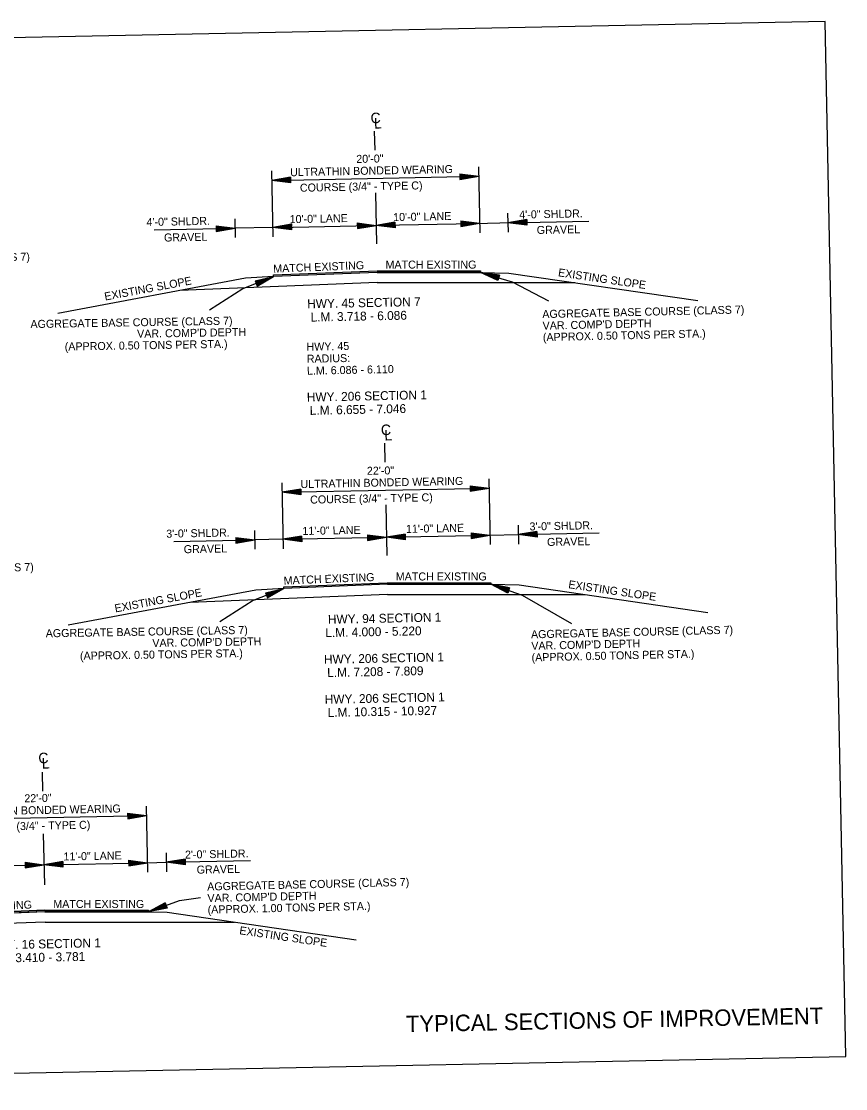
# Model space of a CAD drawing. Extents: x 174 to 869, y -36 to 177.
# Drawn here: x 606.8 to 694.4, y 60.6 to 174 of the extents above; entities that cross this region are included whole.
import ezdxf

# ---------------------------------------------------------------- set-up
doc = ezdxf.new("R2010")
doc.units = 0
for name, color, linetype in [('Default', 7, 'Continuous'), ('DSN_DRFT_Common-Annotations', 7, 'Continuous'), ('DSN_DRFT_Common-Line', 7, 'Continuous'), ('DSN_DRFT_Dimension', 7, 'Continuous'), ('SHET_Border-Text', 7, 'Continuous')]:
    doc.layers.add(name, color=color, linetype=linetype)

msp = doc.modelspace()

# ---------------------------------------------------------------- linework, layer by layer
at = {"layer": 'Default'}
for p, q in [((633.63, 146.84), (630.37, 145.54)), ((631.66, 146.38), (633.63, 146.84)), ((631.66, 146.38), (631.88, 145.82)), ((631.68, 146.33), (633.32, 146.72)), ((631.7, 146.28), (633, 146.59)), ((631.71, 146.24), (632.69, 146.46)), ((631.73, 146.19), (632.37, 146.34)), ((631.81, 146.01), (632.37, 146.34)), ((631.82, 145.96), (632.69, 146.46)), ((631.84, 145.91), (633, 146.59)), ((631.86, 145.87), (633.32, 146.72)), ((631.88, 145.82), (633.63, 146.84)), ((655.63, 147.28), (658.99, 146.29)), ((657.63, 147), (655.63, 147.28)), ((657.46, 146.43), (655.63, 147.28)), ((657.62, 146.95), (655.95, 147.19)), ((657.47, 146.48), (655.95, 147.19)), ((657.49, 146.52), (656.28, 147.09)), ((657.6, 146.91), (656.28, 147.09)), ((657.59, 146.86), (656.6, 147)), ((657.5, 146.57), (656.6, 147)), ((657.52, 146.62), (656.92, 146.9)), ((657.57, 146.81), (656.92, 146.9)), ((657.53, 146.67), (657.24, 146.8)), ((657.56, 146.76), (657.24, 146.8)), ((657.63, 147), (657.46, 146.43)), ((658.99, 146.29), (662.83, 144.28)), ((630.37, 145.54), (626.83, 143.27)), ((631.75, 146.14), (632.06, 146.22)), ((631.79, 146.05), (632.06, 146.22)), ((634.72, 113.71), (631.47, 112.42)), ((632.76, 113.25), (634.72, 113.71)), ((632.77, 113.21), (634.41, 113.59)), ((632.79, 113.16), (634.09, 113.46)), ((632.94, 112.79), (634.09, 113.46)), ((632.96, 112.74), (634.41, 113.59)), ((632.98, 112.7), (634.72, 113.71)), ((656.72, 114.15), (660.03, 113.01)), ((658.71, 113.79), (656.72, 114.15)), ((658.51, 113.22), (656.72, 114.15)), ((658.69, 113.74), (657.04, 114.05)), ((658.53, 113.27), (657.04, 114.05)), ((658.55, 113.32), (657.36, 113.93)), ((658.68, 113.69), (657.36, 113.93)), ((658.66, 113.64), (657.68, 113.83)), ((658.56, 113.36), (657.68, 113.83)), ((658.58, 113.41), (658, 113.72)), ((658.64, 113.6), (658, 113.72)), ((658.6, 113.46), (658.31, 113.61)), ((658.63, 113.55), (658.31, 113.61)), ((658.71, 113.79), (658.51, 113.22)), ((631.47, 112.42), (627.92, 110.15)), ((632.76, 113.25), (632.98, 112.7)), ((632.81, 113.11), (633.79, 113.34)), ((632.83, 113.06), (633.47, 113.22)), ((632.85, 113.02), (633.16, 113.09)), ((632.88, 112.93), (633.16, 113.09)), ((632.9, 112.88), (633.47, 113.22)), ((632.92, 112.84), (633.79, 113.34)), ((660.03, 113.01), (665.3, 109.98)), ((620.33, 79.36), (623.62, 80.55)), ((623.62, 80.55), (625.86, 80.9)), ((622.11, 80.32), (620.33, 79.36)), ((622.31, 79.76), (620.33, 79.36)), ((622.12, 80.27), (620.64, 79.47)), ((622.29, 79.8), (620.64, 79.47)), ((622.14, 80.23), (620.97, 79.59)), ((622.28, 79.85), (620.97, 79.59)), ((622.16, 80.18), (621.28, 79.7)), ((622.26, 79.9), (621.28, 79.7)), ((622.18, 80.13), (621.6, 79.82)), ((622.24, 79.95), (621.6, 79.82)), ((622.19, 80.08), (621.91, 79.93)), ((622.22, 79.99), (621.91, 79.93)), ((622.11, 80.32), (622.31, 79.76))]:
    msp.add_line(p, q, dxfattribs=at)
at = {"layer": 'DSN_DRFT_Common-Line'}
for p, q in [((644.32, 162.29), (644.37, 160.26)), ((633.41, 158.06), (633.55, 151.06)), ((655.4, 158.5), (655.54, 151.5)), ((644.46, 155.74), (644.56, 150.33)), ((658.5, 153.56), (658.54, 151.56)), ((629.51, 152.98), (629.55, 150.98)), ((630.63, 146.67), (610.71, 142.93)), ((633.63, 146.84), (630.63, 146.67)), ((644.62, 147.28), (633.63, 146.84)), ((644.62, 147.28), (655.63, 147.28)), ((655.63, 147.28), (658.63, 147.22)), ((658.63, 147.22), (678.69, 144.29)), ((644.65, 146.2), (623.68, 145.36)), ((644.65, 146.2), (665.63, 146.2)), ((645.42, 129.16), (645.46, 127.13)), ((634.5, 124.93), (634.64, 117.93)), ((656.5, 125.37), (656.64, 118.37)), ((645.55, 122.61), (645.66, 117.2)), ((659.6, 120.43), (659.64, 118.43)), ((631.6, 119.87), (631.64, 117.87)), ((631.73, 113.53), (611.8, 109.8)), ((634.72, 113.71), (631.73, 113.53)), ((645.72, 114.15), (634.72, 113.71)), ((645.72, 114.15), (656.72, 114.15)), ((656.72, 114.15), (659.72, 114.09)), ((659.72, 114.09), (679.78, 111.16)), ((645.74, 113.07), (624.77, 112.23)), ((645.74, 113.07), (666.72, 113.07)), ((609.03, 94.19), (609.07, 92.17)), ((620.1, 90.58), (620.24, 83.58)), ((609.16, 87.65), (609.27, 82.24)), ((622.2, 85.62), (622.24, 83.62)), ((609.32, 79.53), (598.33, 79.09)), ((609.32, 79.53), (620.32, 79.53)), ((620.32, 79.53), (620.33, 79.36)), ((609.35, 78.28), (589.25, 77.47)), ((609.33, 79.36), (598.33, 78.92)), ((609.33, 79.36), (620.33, 79.36)), ((609.35, 78.28), (629.47, 78.28)), ((620.33, 79.36), (622.33, 79.32)), ((622.33, 79.32), (642.39, 76.39))]:
    msp.add_line(p, q, dxfattribs=at)
for points in [[(522.25, 170.55), (524.45, 60.58), (694.42, 63.98), (692.22, 173.95)], [(655.63, 147.28), (644.62, 147.28), (633.63, 146.84), (633.63, 147.01), (644.62, 147.45), (655.62, 147.45)], [(656.72, 114.15), (645.72, 114.15), (634.72, 113.71), (634.72, 113.88), (645.71, 114.32), (656.72, 114.32)], [(620.33, 79.36), (609.33, 79.36), (598.33, 78.92), (598.33, 79.09), (609.32, 79.53), (620.32, 79.53)]]:
    msp.add_lwpolyline(points, close=True, dxfattribs=at)
at = {"layer": 'DSN_DRFT_Dimension'}
for p, q in [((653.42, 157.76), (655.42, 157.5)), ((653.42, 157.76), (653.43, 157.16)), ((653.42, 157.71), (655.09, 157.5)), ((653.42, 157.66), (654.74, 157.49)), ((653.42, 157.61), (654.41, 157.48)), ((633.43, 157.06), (655.42, 157.5)), ((635.42, 157.4), (633.43, 157.06)), ((635.43, 156.8), (633.43, 157.06)), ((635.42, 157.35), (633.76, 157.07)), ((635.43, 156.85), (633.76, 157.07)), ((635.42, 157.3), (634.11, 157.08)), ((635.43, 156.9), (634.11, 157.08)), ((635.42, 157.25), (634.44, 157.08)), ((635.43, 156.95), (634.44, 157.08)), ((635.42, 157.2), (634.78, 157.09)), ((635.43, 157), (634.78, 157.09)), ((635.43, 157.15), (635.11, 157.1)), ((635.43, 157.06), (635.11, 157.1)), ((635.42, 157.4), (635.43, 156.8)), ((653.42, 157.56), (654.07, 157.48)), ((653.42, 157.51), (653.74, 157.47)), ((653.42, 157.42), (653.74, 157.47)), ((653.43, 157.16), (655.42, 157.5)), ((653.43, 157.21), (655.09, 157.5)), ((653.43, 157.26), (654.74, 157.49)), ((653.43, 157.36), (654.07, 157.48)), ((653.43, 157.31), (654.41, 157.48)), ((620.92, 151.81), (629.53, 151.98)), ((627.52, 152.24), (629.53, 151.98)), ((627.52, 152.24), (627.53, 151.64)), ((627.52, 152.19), (629.19, 151.98)), ((627.52, 152.14), (628.85, 151.97)), ((627.53, 152.09), (628.52, 151.96)), ((627.53, 152.04), (628.18, 151.96)), ((627.53, 151.99), (627.84, 151.95)), ((627.53, 151.64), (629.53, 151.98)), ((627.53, 151.69), (629.19, 151.98)), ((627.53, 151.75), (628.85, 151.97)), ((627.53, 151.85), (628.18, 151.96)), ((627.53, 151.8), (628.52, 151.96)), ((627.53, 151.9), (627.84, 151.95)), ((633.53, 152.06), (629.53, 151.98)), ((635.52, 152.4), (633.53, 152.06)), ((635.53, 151.8), (633.53, 152.06)), ((635.52, 152.35), (633.86, 152.07)), ((635.53, 151.85), (633.86, 152.07)), ((634.03, 152.07), (644.03, 152.27)), ((635.52, 152.3), (634.21, 152.08)), ((635.53, 151.9), (634.21, 152.08)), ((635.52, 152.25), (634.54, 152.08)), ((635.53, 151.95), (634.54, 152.08)), ((635.52, 152.2), (634.88, 152.09)), ((635.53, 152.01), (634.88, 152.09)), ((635.53, 152.15), (635.21, 152.1)), ((635.53, 152.06), (635.21, 152.1)), ((635.52, 152.4), (635.53, 151.8)), ((642.52, 152.54), (644.52, 152.28)), ((642.52, 152.54), (642.53, 151.94)), ((642.52, 152.49), (644.19, 152.28)), ((642.52, 152.44), (643.85, 152.27)), ((642.52, 152.39), (643.51, 152.26)), ((642.52, 152.34), (643.18, 152.26)), ((642.52, 152.29), (642.84, 152.25)), ((642.53, 151.94), (644.52, 152.28)), ((642.53, 151.99), (644.19, 152.28)), ((642.53, 152.04), (643.85, 152.27)), ((642.53, 152.15), (643.18, 152.26)), ((642.53, 152.09), (643.51, 152.26)), ((642.53, 152.2), (642.84, 152.25)), ((646.52, 152.62), (644.52, 152.28)), ((646.53, 152.02), (644.52, 152.28)), ((646.52, 152.57), (644.86, 152.29)), ((646.53, 152.07), (644.86, 152.29)), ((645.02, 152.29), (655.02, 152.49)), ((646.52, 152.52), (645.2, 152.3)), ((646.53, 152.12), (645.2, 152.3)), ((646.52, 152.47), (645.54, 152.3)), ((646.53, 152.17), (645.54, 152.3)), ((646.52, 152.42), (645.87, 152.31)), ((646.53, 152.23), (645.87, 152.31)), ((646.52, 152.37), (646.21, 152.32)), ((646.53, 152.28), (646.21, 152.32)), ((646.52, 152.62), (646.53, 152.02)), ((653.52, 152.76), (655.52, 152.5)), ((653.52, 152.76), (653.53, 152.16)), ((653.52, 152.71), (655.19, 152.5)), ((653.52, 152.66), (654.84, 152.49)), ((653.52, 152.61), (654.51, 152.48)), ((653.52, 152.56), (654.17, 152.48)), ((653.52, 152.51), (653.84, 152.47)), ((653.52, 152.42), (653.84, 152.47)), ((653.53, 152.16), (655.52, 152.5)), ((653.53, 152.21), (655.19, 152.5)), ((653.53, 152.26), (654.84, 152.49)), ((653.53, 152.37), (654.17, 152.48)), ((653.53, 152.31), (654.51, 152.48)), ((655.02, 152.49), (659.02, 152.57)), ((660.52, 152.9), (658.52, 152.56)), ((658.52, 152.56), (667.13, 152.74)), ((660.53, 152.3), (658.52, 152.56)), ((660.52, 152.85), (658.86, 152.57)), ((660.53, 152.35), (658.86, 152.57)), ((660.52, 152.8), (659.2, 152.58)), ((660.53, 152.4), (659.2, 152.58)), ((660.52, 152.75), (659.53, 152.58)), ((660.52, 152.45), (659.53, 152.58)), ((660.52, 152.7), (659.87, 152.59)), ((660.52, 152.51), (659.87, 152.59)), ((660.52, 152.65), (660.21, 152.6)), ((660.52, 152.56), (660.21, 152.6)), ((660.52, 152.9), (660.53, 152.3)), ((634.52, 123.93), (656.52, 124.37)), ((636.51, 124.27), (634.52, 123.93)), ((636.53, 123.67), (634.52, 123.93)), ((636.51, 124.22), (634.85, 123.94)), ((636.52, 123.72), (634.85, 123.94)), ((636.52, 124.17), (635.2, 123.95)), ((636.52, 123.77), (635.2, 123.95)), ((636.52, 124.12), (635.53, 123.95)), ((636.52, 123.82), (635.53, 123.95)), ((636.52, 124.07), (635.87, 123.96)), ((636.52, 123.87), (635.87, 123.96)), ((636.52, 124.02), (636.2, 123.97)), ((636.52, 123.93), (636.2, 123.97)), ((636.51, 124.27), (636.53, 123.67)), ((654.51, 124.63), (656.52, 124.37)), ((654.51, 124.63), (654.52, 124.03)), ((654.51, 124.58), (656.18, 124.37)), ((654.51, 124.53), (655.84, 124.36)), ((654.51, 124.48), (655.5, 124.35)), ((654.51, 124.43), (655.17, 124.35)), ((654.52, 124.38), (654.83, 124.34)), ((654.52, 124.03), (656.52, 124.37)), ((654.52, 124.08), (656.18, 124.37)), ((654.52, 124.13), (655.84, 124.36)), ((654.52, 124.23), (655.17, 124.35)), ((654.52, 124.18), (655.5, 124.35)), ((654.52, 124.29), (654.83, 124.34)), ((629.62, 119.13), (631.62, 118.87)), ((629.62, 119.13), (629.63, 118.53)), ((629.62, 119.08), (631.29, 118.87)), ((636.61, 119.27), (634.62, 118.93)), ((634.62, 118.93), (645.62, 119.15)), ((636.61, 119.22), (634.95, 118.94)), ((636.62, 119.17), (635.3, 118.95)), ((636.62, 119.12), (635.63, 118.95)), ((636.62, 119.07), (635.97, 118.96)), ((636.61, 119.27), (636.63, 118.67)), ((643.61, 119.41), (645.62, 119.15)), ((643.61, 119.41), (643.62, 118.81)), ((643.61, 119.36), (645.28, 119.15)), ((643.61, 119.31), (644.94, 119.14)), ((643.62, 119.26), (644.61, 119.13)), ((643.62, 119.21), (644.27, 119.13)), ((643.62, 119.16), (643.93, 119.12)), ((643.62, 118.81), (645.62, 119.15)), ((643.62, 118.86), (645.28, 119.15)), ((643.62, 118.91), (644.94, 119.14)), ((643.62, 119.02), (644.27, 119.13)), ((643.62, 118.96), (644.61, 119.13)), ((643.62, 119.07), (643.93, 119.12)), ((647.61, 119.49), (645.62, 119.15)), ((645.62, 119.15), (656.62, 119.37)), ((647.62, 118.89), (645.62, 119.15)), ((647.61, 119.44), (645.95, 119.16)), ((647.62, 118.94), (645.95, 119.16)), ((647.61, 119.39), (646.3, 119.17)), ((647.62, 118.99), (646.3, 119.17)), ((647.61, 119.34), (646.63, 119.17)), ((647.62, 119.04), (646.63, 119.17)), ((647.62, 119.29), (646.97, 119.18)), ((647.62, 119.1), (646.97, 119.18)), ((647.62, 119.24), (647.3, 119.19)), ((647.62, 119.15), (647.3, 119.19)), ((647.61, 119.49), (647.62, 118.89)), ((654.61, 119.63), (656.62, 119.37)), ((654.61, 119.63), (654.62, 119.03)), ((654.61, 119.58), (656.28, 119.37)), ((654.61, 119.53), (655.94, 119.36)), ((654.61, 119.48), (655.6, 119.35)), ((654.61, 119.43), (655.27, 119.35)), ((654.62, 119.38), (654.93, 119.34)), ((654.62, 119.03), (656.62, 119.37)), ((654.62, 119.08), (656.28, 119.37)), ((654.62, 119.13), (655.94, 119.36)), ((654.62, 119.24), (655.27, 119.35)), ((654.62, 119.18), (655.6, 119.35)), ((654.62, 119.29), (654.93, 119.34)), ((656.62, 119.37), (659.62, 119.43)), ((661.61, 119.77), (659.62, 119.43)), ((659.62, 119.43), (668.22, 119.61)), ((661.62, 119.17), (659.62, 119.43)), ((661.61, 119.72), (659.95, 119.44)), ((661.62, 119.22), (659.95, 119.44)), ((661.61, 119.67), (660.29, 119.45)), ((661.62, 119.27), (660.29, 119.45)), ((661.61, 119.62), (660.63, 119.45)), ((661.62, 119.32), (660.63, 119.45)), ((661.61, 119.57), (660.96, 119.46)), ((661.62, 119.38), (660.96, 119.46)), ((661.61, 119.52), (661.3, 119.47)), ((661.62, 119.43), (661.3, 119.47)), ((661.61, 119.77), (661.62, 119.17)), ((623.01, 118.7), (631.62, 118.87)), ((629.62, 119.03), (630.94, 118.86)), ((629.62, 118.98), (630.61, 118.85)), ((629.62, 118.93), (630.27, 118.85)), ((629.62, 118.88), (629.94, 118.84)), ((629.62, 118.63), (630.94, 118.86)), ((629.62, 118.74), (630.27, 118.85)), ((629.62, 118.68), (630.61, 118.85)), ((629.62, 118.79), (629.94, 118.84)), ((629.63, 118.53), (631.62, 118.87)), ((629.63, 118.58), (631.29, 118.87)), ((634.62, 118.93), (631.62, 118.87)), ((636.63, 118.67), (634.62, 118.93)), ((636.62, 118.72), (634.95, 118.94)), ((636.62, 118.77), (635.3, 118.95)), ((636.62, 118.82), (635.63, 118.95)), ((636.62, 118.88), (635.97, 118.96)), ((636.62, 119.02), (636.3, 118.97)), ((636.62, 118.93), (636.3, 118.97)), ((598.13, 89.14), (620.12, 89.58)), ((618.12, 89.84), (620.12, 89.58)), ((618.12, 89.84), (618.13, 89.24)), ((618.12, 89.79), (619.79, 89.57)), ((618.12, 89.74), (619.45, 89.56)), ((618.12, 89.69), (619.11, 89.56)), ((618.12, 89.63), (618.77, 89.55)), ((618.12, 89.58), (618.44, 89.54)), ((618.13, 89.24), (620.12, 89.58)), ((618.13, 89.29), (619.79, 89.57)), ((618.12, 89.49), (618.44, 89.54)), ((618.13, 89.34), (619.45, 89.56)), ((618.13, 89.39), (619.11, 89.56)), ((618.13, 89.44), (618.77, 89.55)), ((598.23, 84.14), (609.23, 84.36)), ((607.22, 84.62), (609.23, 84.36)), ((607.22, 84.62), (607.23, 84.02)), ((607.22, 84.57), (608.89, 84.35)), ((607.22, 84.52), (608.55, 84.34)), ((607.22, 84.47), (608.21, 84.34)), ((607.22, 84.41), (607.88, 84.33)), ((607.23, 84.02), (609.23, 84.36)), ((607.23, 84.36), (607.54, 84.32)), ((607.23, 84.07), (608.89, 84.35)), ((607.23, 84.12), (608.55, 84.34)), ((607.23, 84.17), (608.21, 84.34)), ((607.23, 84.22), (607.88, 84.33)), ((607.23, 84.27), (607.54, 84.32)), ((611.22, 84.7), (609.23, 84.36)), ((609.23, 84.36), (620.22, 84.58)), ((611.23, 84.1), (609.23, 84.36)), ((611.22, 84.65), (609.56, 84.36)), ((611.23, 84.15), (609.56, 84.36)), ((611.22, 84.6), (609.9, 84.37)), ((611.23, 84.2), (609.9, 84.37)), ((611.22, 84.55), (610.24, 84.38)), ((611.23, 84.25), (610.24, 84.38)), ((611.22, 84.49), (610.58, 84.38)), ((611.23, 84.3), (610.58, 84.38)), ((611.22, 84.44), (610.91, 84.39)), ((611.23, 84.35), (610.91, 84.39)), ((611.22, 84.7), (611.23, 84.1)), ((618.22, 84.84), (620.22, 84.58)), ((618.22, 84.84), (618.23, 84.24)), ((618.22, 84.79), (619.89, 84.57)), ((618.22, 84.74), (619.55, 84.56)), ((618.22, 84.69), (619.21, 84.56)), ((618.22, 84.63), (618.87, 84.55)), ((618.22, 84.58), (618.54, 84.54)), ((618.22, 84.49), (618.54, 84.54)), ((618.23, 84.24), (620.22, 84.58)), ((618.23, 84.29), (619.89, 84.57)), ((618.23, 84.34), (619.55, 84.56)), ((618.23, 84.39), (619.21, 84.56)), ((618.23, 84.44), (618.87, 84.55)), ((620.22, 84.58), (622.22, 84.62)), ((624.22, 84.96), (622.22, 84.62)), ((622.22, 84.62), (631.16, 84.8)), ((624.23, 84.36), (622.22, 84.62)), ((624.22, 84.91), (622.56, 84.62)), ((624.23, 84.41), (622.56, 84.62)), ((624.22, 84.86), (622.9, 84.63)), ((624.23, 84.46), (622.9, 84.63)), ((624.22, 84.81), (623.23, 84.64)), ((624.23, 84.51), (623.23, 84.64)), ((624.22, 84.75), (623.57, 84.64)), ((624.22, 84.56), (623.57, 84.64)), ((624.22, 84.7), (623.91, 84.65)), ((624.22, 84.61), (623.91, 84.65)), ((624.22, 84.96), (624.23, 84.36))]:
    msp.add_line(p, q, dxfattribs=at)

# ---------------------------------------------------------------- texts
at = {"layer": 'Default'}
for s, height, rotation, p in [('C', 1.12, 2.2915, (643.95, 163.11)), ('L', 1.12, 2.2915, (644.31, 162.55)), ('AGGREGATE BASE COURSE (CLASS 7)', 0.85, 1.3198, (586.27, 148.04)), ('AGGREGATE BASE COURSE (CLASS 7)', 0.85, 1.3198, (662.19, 142.43)), ('AGGREGATE BASE COURSE (CLASS 7)', 0.85, 0.9717, (607.8, 141.37)), ("VAR. COMP'D DEPTH", 0.85, 1.3198, (662.22, 141.2)), ("VAR. COMP'D DEPTH", 0.85, 0.9717, (619.13, 140.34)), ('(APPROX. 0.50 TONS PER STA.)', 0.85, 1.3198, (662.25, 139.98)), ('(APPROX. 0.50 TONS PER STA.)', 0.85, 0.9717, (611.44, 138.98)), ('C', 1.12, 2.2915, (645.05, 129.98)), ('L', 1.12, 2.2915, (645.41, 129.42)), ('AGGREGATE BASE COURSE (CLASS 7)', 0.85, 1.3198, (586.68, 115.08)), ('AGGREGATE BASE COURSE (CLASS 7)', 0.85, 0.9717, (609.42, 108.52)), ('AGGREGATE BASE COURSE (CLASS 7)', 0.85, 1.3198, (660.99, 108.41)), ("VAR. COMP'D DEPTH", 0.85, 0.9717, (620.75, 107.49)), ("VAR. COMP'D DEPTH", 0.85, 1.3198, (661.02, 107.19)), ('(APPROX. 0.50 TONS PER STA.)', 0.85, 0.9717, (613.06, 106.13)), ('(APPROX. 0.50 TONS PER STA.)', 0.85, 1.3198, (661.05, 105.96)), ('AGGREGATE BASE COURSE (CLASS 7)', 0.85, 1.3198, (626.58, 81.62)), ("VAR. COMP'D DEPTH", 0.85, 1.3198, (626.61, 80.39)), ('(APPROX. 1.00 TONS PER STA.)', 0.85, 1.3198, (626.63, 79.17))]:
    msp.add_text(s, height=height, rotation=rotation, dxfattribs=at).set_placement(p)
at = {"layer": 'DSN_DRFT_Common-Annotations'}
for s, height, rotation, p in [('20\'-0"', 0.85, 1.1458, (642.42, 158.91)), ('ULTRATHIN BONDED WEARING', 0.85, 1.1458, (635.39, 157.5)), ('COURSE (3/4" - TYPE C)', 0.85, 1.1458, (636.43, 155.85)), ('4\'-0" SHLDR.', 0.85, 1.1458, (620.13, 152.21)), ('10\'-0" LANE', 0.85, 1.1458, (635.34, 152.51)), ('10\'-0" LANE', 0.85, 1.1458, (646.34, 152.73)), ('4\'-0" SHLDR.', 0.85, 1.1458, (659.74, 153)), ('GRAVEL', 0.85, 1.1458, (661.6, 151.36)), ('GRAVEL', 0.85, 1.1458, (621.99, 150.56)), ('MATCH EXISTING', 0.85, 2.2915, (633.61, 147.25)), ('EXISTING SLOPE', 0.85, 351.6838, (663.82, 146.88)), ('EXISTING SLOPE', 0.85, 10.6078, (615.73, 144.29)), ('HWY. 45 SECTION 7', 0.943, 1.1458, (637.21, 143.47)), ('L.M. 3.718 - 6.086', 0.943, 1.1458, (637.57, 142.06)), ('HWY. 45', 0.85, 1.1458, (637.13, 138.96)), ('RADIUS:', 0.85, 1.1458, (637.16, 137.68)), ('L.M. 6.086 - 6.110', 0.85, 1.1458, (637.18, 136.41)), ('HWY. 206 SECTION 1', 0.943, 1.1458, (637.17, 133.56)), ('L.M. 6.655 - 7.046', 0.943, 1.1458, (637.48, 132.15)), ('22\'-0"', 0.85, 1.1458, (643.55, 125.78)), ('ULTRATHIN BONDED WEARING', 0.85, 1.1458, (636.49, 124.37)), ('COURSE (3/4" - TYPE C)', 0.85, 1.1458, (637.52, 122.72)), ('11\'-0" LANE', 0.85, 1.1458, (636.7, 119.39)), ('11\'-0" LANE', 0.85, 1.1458, (647.7, 119.61)), ('3\'-0" SHLDR.', 0.85, 1.1458, (660.83, 119.87)), ('3\'-0" SHLDR.', 0.85, 1.1458, (622.23, 119.1)), ('GRAVEL', 0.85, 1.1458, (662.69, 118.22)), ('GRAVEL', 0.85, 1.1458, (624.09, 117.45)), ('MATCH EXISTING', 0.85, 2.2915, (634.71, 114.12)), ('EXISTING SLOPE', 0.85, 351.6838, (664.91, 113.75)), ('EXISTING SLOPE', 0.85, 10.6078, (616.82, 111.16)), ('HWY. 94 SECTION 1', 0.943, 1.1458, (639.41, 109.96)), ('L.M. 4.000 - 5.220', 0.943, 1.1458, (639.13, 108.54)), ('HWY. 206 SECTION 1', 0.943, 1.1458, (638.99, 105.71)), ('L.M. 7.208 - 7.809', 0.943, 1.1458, (639.33, 104.3)), ('HWY. 206 SECTION 1', 0.943, 1.1458, (639.07, 101.46)), ('L.M. 10.315 - 10.927', 0.943, 1.1458, (639.38, 100.06)), ('C', 1.12, 2.2915, (608.65, 95.12)), ('L', 1.12, 2.2915, (609.01, 94.56)), ('22\'-0"', 0.85, 1.1458, (607.15, 90.99)), ('ULTRATHIN BONDED WEARING', 0.85, 1.1458, (600.09, 89.57)), ('COURSE (3/4" - TYPE C)', 0.85, 1.1458, (601.13, 87.93)), ('11\'-0" LANE', 0.85, 1.1458, (611.31, 84.81)), ('2\'-0" SHLDR.', 0.85, 1.1458, (624.22, 85.01)), ('GRAVEL', 0.85, 1.1458, (625.46, 83.41)), ('MATCH EXISTING', 0.85, 2.2915, (598.31, 79.33)), ('EXISTING SLOPE', 0.85, 351.6838, (629.95, 76.99)), ('HWY. 16 SECTION 1', 0.943, 1.1458, (603.23, 75.36)), ('L.M. 3.410 - 3.781', 0.943, 1.1458, (603.39, 73.95))]:
    msp.add_text(s, height=height, rotation=rotation, dxfattribs=at).set_placement(p)
for p in [(645.52, 147.69), (646.61, 114.56), (610.22, 79.77)]:
    msp.add_text('MATCH EXISTING', height=0.85, dxfattribs=at).set_placement(p)
at = {"layer": 'SHET_Border-Text'}
msp.add_text('TYPICAL SECTIONS OF IMPROVEMENT', height=1.75, rotation=1.1458, dxfattribs=at).set_placement((647.71, 66.57))

doc.saveas('drawing.dxf')
